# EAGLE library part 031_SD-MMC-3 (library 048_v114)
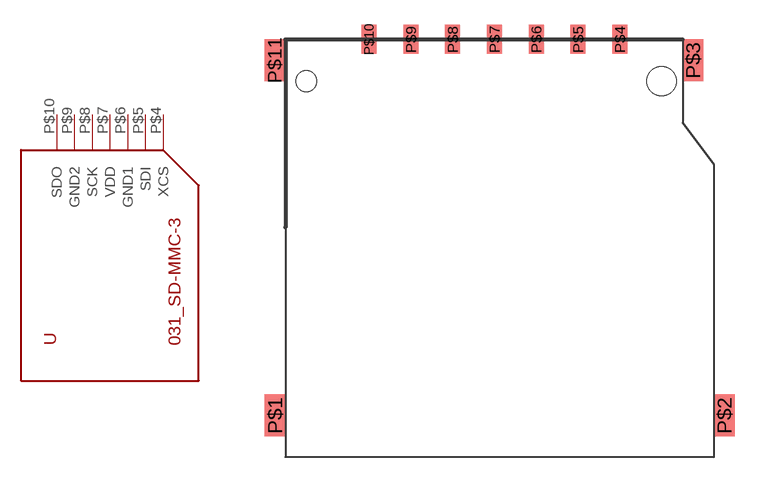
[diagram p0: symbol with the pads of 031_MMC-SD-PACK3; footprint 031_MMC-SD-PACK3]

Designator prefix -

## 031_SD-MMC-3  [031_MMC-SD-PACK3]
P$4  XCS  in
P$5  SDI  in
P$6  GND1  pwr
P$7  VDD  pwr
P$8  SCK  in
P$9  GND2  pwr
P$10  SDO  out

## Footprint 031_MMC-SD-PACK3 (pad centres in mm)
smd 1.27 x 2.54: P$1 -0.635,2.54; P$2 26.67,2.54; P$3 24.765,24.13; P$11 -0.635,24.13
smd 0.914 x 1.778: P$4 20.32,25.4; P$5 17.78,25.4; P$6 15.24,25.4; P$7 12.7,25.4; P$8 10.16,25.4; P$9 7.62,25.4; P$10 5.08,25.4
hole 1.27 at 1.27,22.86
hole 1.778 at 22.86,22.86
